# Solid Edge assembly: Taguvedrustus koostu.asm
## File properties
Author: Türk
Template: Iso Assembly.asm
Last saved by: Türk
Revision: 17
Application: Solid Edge
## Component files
Hoidja.tagu.par
si.par
Poldikoostu8.asm
Poldikoostu6.asm
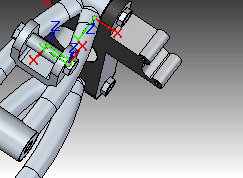
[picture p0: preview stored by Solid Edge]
